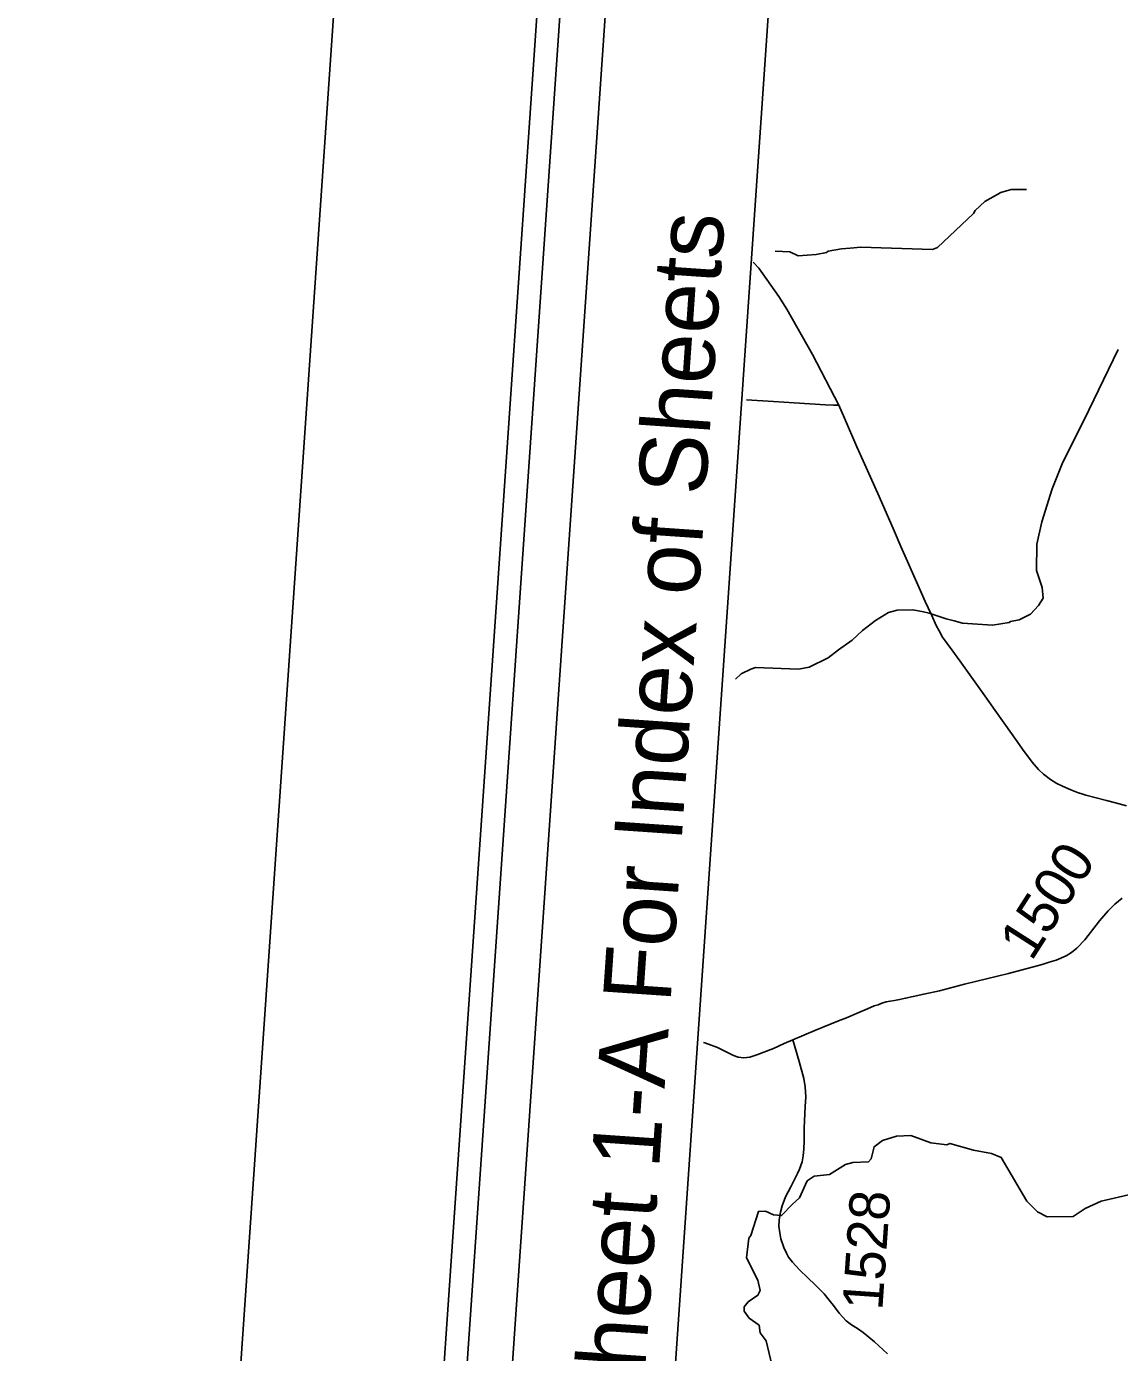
# Model space of a CAD drawing. Extents: x 2598107 to 2605763, y 726018 to 731166.
# Drawn here: x 2598106.6 to 2598378.7, y 728163.4 to 728493.7 of the extents above; entities that cross this region are included whole.
import ezdxf

# ---------------------------------------------------------------- set-up
doc = ezdxf.new("R2010")
doc.units = 0
for name, color, linetype in [('Old_Level_1', 7, 'Continuous'), ('Old_Level_29', 7, 'Continuous'), ('Old_Level_31', 7, 'Continuous'), ('Old_Level_32', 7, 'Continuous'), ('Old_Level_50', 7, 'Continuous'), ('Old_Level_59', 7, 'Continuous'), ('Sheet Cutting Line CELL', 7, 'Continuous'), ('Sheet Plot Border Inside CELL', 7, 'Continuous'), ('Sheet Plot Border Outside CELL', 7, 'Continuous'), ('Sheet Title CELL', 7, 'Continuous')]:
    doc.layers.add(name, color=color, linetype=linetype)

msp = doc.modelspace()

# ---------------------------------------------------------------- linework, layer by layer
at = {"layer": 'Old_Level_1'}
msp.add_line((2598299.76, 728619.7), (2598252.58, 727934.77), dxfattribs=at)
at = {"layer": 'Old_Level_29'}
for points in [[(2598308.82, 728399.4), (2598302.27, 728411.98), (2598295.89, 728423.25), (2598293.94, 728426.41), (2598288.91, 728433.5), (2598287.51, 728435.02)], [(2598380.46, 728299.6), (2598377.77, 728300.33), (2598375.51, 728300.89), (2598370.39, 728302.24), (2598369.57, 728302.49), (2598368.26, 728302.94), (2598366.62, 728303.56), (2598364.52, 728304.46), (2598363.17, 728305.13), (2598361.52, 728306.16), (2598359.79, 728307.47), (2598358.57, 728308.63), (2598357, 728310.47), (2598354.57, 728313.74), (2598353.29, 728315.57), (2598350.04, 728320.15), (2598347.77, 728323.36), (2598345.17, 728326.99), (2598338.94, 728335.73), (2598336.99, 728338.44), (2598334.69, 728341.63), (2598333.85, 728343.16), (2598333.12, 728344.54), (2598331.97, 728346.98), (2598331.08, 728348.89), (2598330.38, 728350.47), (2598328.83, 728353.92), (2598324.32, 728364.18), (2598322.6, 728368.1), (2598318.89, 728376.61), (2598314.89, 728385.55), (2598313.33, 728388.97), (2598310.25, 728396.12), (2598308.82, 728399.4)]]:
    msp.add_lwpolyline(points, dxfattribs=at)
at = {"layer": 'Old_Level_31'}
msp.add_line((2598294.18, 728196.36), (2598294.18, 728196.36), dxfattribs=at)
at = {"layer": 'Old_Level_32'}
for points in [[(2598308.82, 728399.4), (2598307.53, 728399.36), (2598305.56, 728399.44), (2598297.7, 728399.93), (2598292.59, 728400.28), (2598285.85, 728400.7)], [(2598297.43, 728241.28), (2598302.86, 728243.61), (2598308.79, 728246.05), (2598310.79, 728246.76), (2598313.82, 728248.12), (2598315.95, 728249.01), (2598317.66, 728249.74), (2598318.66, 728250.06), (2598319.56, 728250.44), (2598320.67, 728250.75), (2598321.66, 728250.98), (2598322.74, 728251.14), (2598323.98, 728251.35), (2598325.47, 728251.66), (2598327.32, 728252.1), (2598329.98, 728252.7), (2598333.89, 728253.55), (2598340.13, 728255.14), (2598351.07, 728257.87), (2598359.45, 728260.09), (2598361.22, 728260.64), (2598362.99, 728261.18), (2598365.44, 728262.27), (2598366.75, 728263.05), (2598368.1, 728264.12), (2598370.07, 728266.22), (2598373.74, 728270.91), (2598375.88, 728273.42), (2598377.6, 728275.09), (2598379.39, 728276.56)], [(2598275.14, 728240.66), (2598275.46, 728240.56), (2598278.6, 728239.38), (2598282.59, 728237.39), (2598283.77, 728237.01), (2598285.15, 728236.81), (2598286.69, 728236.96), (2598288.46, 728237.61), (2598292.57, 728239.17), (2598295.21, 728240.39), (2598297.43, 728241.28)], [(2598297.43, 728241.28), (2598298.97, 728235.91), (2598300.14, 728231.67), (2598300.5, 728229.6), (2598300.6, 728227.1), (2598300.5, 728224.72), (2598300.32, 728221.14), (2598300.21, 728219.3), (2598300.21, 728216.08), (2598300.15, 728214.14), (2598299.94, 728212.4), (2598299.68, 728210.89), (2598299.08, 728209.11), (2598298.56, 728208.05), (2598296.9, 728204.73), (2598295.53, 728202.21), (2598294.71, 728199.95), (2598294.31, 728198.41), (2598293.96, 728196.52), (2598293.96, 728196.29)], [(2598293.96, 728196.29), (2598293.92, 728194.88), (2598294.18, 728193.22), (2598294.4, 728191.75), (2598295.11, 728189.57), (2598295.81, 728188.17), (2598296.35, 728187.22), (2598297.27, 728185.96), (2598299.08, 728184), (2598301.14, 728182.02), (2598302.94, 728180.27), (2598305.22, 728178.01), (2598306.44, 728176.48), (2598307.5, 728175.17), (2598308.96, 728173.22), (2598309.8, 728172.21), (2598310.69, 728171.34), (2598312.04, 728170.34), (2598313.53, 728169.38), (2598314.93, 728168.38), (2598317.76, 728166.09), (2598320.95, 728163.08)]]:
    msp.add_lwpolyline(points, dxfattribs=at)
at = {"layer": 'Old_Level_50'}
msp.add_line((2598294.01, 728196.26), (2598294.01, 728196.26), dxfattribs=at)
at = {"layer": 'Old_Level_59'}
for points in [[(2598355.57, 728453.05), (2598351.78, 728453.1), (2598349.22, 728452.34), (2598345.17, 728450.13), (2598342.8, 728447.85), (2598342.4, 728447.12), (2598333.42, 728438.61), (2598332.18, 728438.16), (2598314.33, 728438.74), (2598311.7, 728438.5), (2598309.54, 728438.35), (2598306.19, 728437.74), (2598305.8, 728437.38), (2598303.16, 728436.88), (2598298.74, 728436.58), (2598296.61, 728437.56), (2598292.96, 728437.73)], [(2598378.43, 728413.22), (2598371.12, 728398.09), (2598364.48, 728384.8), (2598361.94, 728378.51), (2598359.4, 728370.32), (2598358.15, 728364.73), (2598358.04, 728358.18), (2598359.51, 728353.97), (2598359.76, 728351.31), (2598358.58, 728349.48), (2598356.59, 728347.31), (2598353.78, 728345.93), (2598351.61, 728345.52), (2598351.22, 728345.29), (2598347.12, 728344.6), (2598339.63, 728345.09), (2598337.54, 728345.68), (2598335.54, 728346.16), (2598331.31, 728347.61), (2598329.92, 728347.92), (2598327.3, 728348.43), (2598323.36, 728348.35), (2598321.18, 728347.7), (2598317.98, 728345.72), (2598314.76, 728343.22), (2598312.16, 728340.83), (2598308.8, 728338.47), (2598306.21, 728336.46), (2598301.45, 728334.16), (2598298.81, 728333.66), (2598288.08, 728334.03), (2598286.89, 728333.59), (2598284.56, 728332.43), (2598283.12, 728331.15)], [(2598370.15, 728199.27), (2598367.18, 728197.3), (2598360.71, 728197.23), (2598358.31, 728198.48), (2598355.67, 728201.13), (2598349.29, 728212.01), (2598346.83, 728213), (2598342.36, 728213.84), (2598336.5, 728215.52), (2598335.74, 728215.18), (2598331.72, 728215.62), (2598326.8, 728217.5), (2598323.23, 728217.29), (2598319.73, 728216.2), (2598317.62, 728214.67), (2598316.87, 728211.68), (2598316.24, 728210.95), (2598312.29, 728210.77), (2598310.49, 728210.23), (2598306.53, 728207.78), (2598302.71, 728207.33), (2598300.99, 728206.16), (2598299.08, 728201.98), (2598297.34, 728200.41), (2598294.58, 728197.54), (2598292.57, 728197.75), (2598290.58, 728198.6), (2598288.8, 728198.57), (2598286.93, 728192.61), (2598286.44, 728191.88)], [(2598405.84, 728188.38), (2598405.23, 728188.41), (2598403.93, 728190.22), (2598401.28, 728192.49), (2598399.18, 728195.99), (2598397.04, 728198.1), (2598392.21, 728201.11), (2598391.39, 728202.03), (2598387.79, 728203.97), (2598385.3, 728203.7), (2598374.19, 728201.1), (2598370.15, 728199.27)], [(2598289.29, 728168.34), (2598289.02, 728170.23), (2598286.49, 728172), (2598285.28, 728173.7), (2598285.31, 728174.83), (2598286.24, 728176.04), (2598288.68, 728177.68), (2598289.23, 728178.91), (2598288.65, 728181.45), (2598285.82, 728187.01), (2598286.44, 728191.88)], [(2598289.29, 728168.34), (2598290.73, 728166.38), (2598292.22, 728160.02), (2598294.1, 728155.26), (2598295.31, 728150.31), (2598296.83, 728147.85), (2598300.78, 728143.49), (2598303.88, 728140.83), (2598304.19, 728139.93), (2598304, 728138.43), (2598302.64, 728135.35), (2598302.53, 728125.43)]]:
    msp.add_lwpolyline(points, dxfattribs=at)
at = {"layer": 'Sheet Cutting Line CELL'}
msp.add_line((2598106.57, 727386.04), (2598366.91, 731166.08), dxfattribs=at)
at = {"layer": 'Sheet Plot Border Inside CELL'}
msp.add_lwpolyline([(2600527.34, 727248.63), (2600784.97, 730989.4), (2598416.61, 731152.51), (2598158.97, 727411.75)], close=True, dxfattribs=at)
at = {"layer": 'Sheet Plot Border Outside CELL'}
msp.add_lwpolyline([(2598366.91, 731166.08), (2598106.57, 727386.04), (2600575.69, 727215.98), (2600836.03, 730996.03)], close=True, dxfattribs=at)
at = {"layer": 'Sheet Title CELL'}
for points in [[(2598418.85, 731101.64), (2598190.02, 727779.46)], [(2598429.3, 731089.62), (2598209.78, 727902.2)]]:
    msp.add_lwpolyline(points, dxfattribs=at)

# ---------------------------------------------------------------- texts
at = {"layer": 'Old_Level_1'}
for s, height, rotation, p in [('1500', 10.145, 57.3831, (2598356.82, 728260.65)), ('1528', 10.003, 86.0601, (2598319.67, 728173.79))]:
    msp.add_text(s, height=height, rotation=rotation, dxfattribs=at).set_placement(p)
at = {"layer": 'Sheet Title CELL'}
msp.add_text('See Sheet 1-A For Index of Sheets', height=16.875, rotation=86.0601, dxfattribs=at).set_placement((2598256.39, 728097.65))

doc.saveas('drawing.dxf')
